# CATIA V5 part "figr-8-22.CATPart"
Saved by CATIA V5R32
Part number: Part1
Bounding box of the stored display mesh (mm): x -60 to 60, y -75 to 75, z 0 to 10
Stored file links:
  D:\PROJECTS\Project 2022\CATIA V5 6R 2022\Resources\Part Files\c08_catia_v5_6r2022_prt\figr-8-22.CATPart
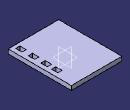
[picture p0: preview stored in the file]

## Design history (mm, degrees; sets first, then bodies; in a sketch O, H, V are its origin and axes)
Body1 (main body)
  Sketch1 on xy-plane, origin (0, 0, 0), H (1, 0, 0), V (0, 1, 0)
    line L1 (60, 75) -> (60, -75)
    line L2 (60, -75) -> (-60, -75)
    line L3 (-60, -75) -> (-60, 75)
    line L4 (-60, 75) -> (60, 75)
    length L2 = 120
    length L1 = 150
    vertical: L1 V, L3 V
    horizontal: L2 H, L4 H
    equidistance: L1 L3 O, L2 L4 O
  Pad1: profile Sketch1, direction (0, 0, 1), length 10
  Sketch2 on end face of Pad1, origin (0, 0, 10), H (1, 0, 0), V (0, 1, 0)
    point P1 (45, -59.5)
    line L1 (50, -52) -> (50, -67)
    line L2 (50, -67) -> (40, -67)
    line L3 (40, -67) -> (40, -52)
    line L4 (40, -52) -> (50, -52)
    reference projected line E1 (-60, -75) -> (60, -75) from edge [face of Pad1 from Sketch1.L2 | end face of Pad1]
    reference projected line E2 (60, -75) -> (60, 75) from edge [face of Pad1 from Sketch1.L1 | end face of Pad1]
    distance L2 E1 = 8
    distance L1 E2 = 10
    length L4 = 10
    length L3 = 15
    vertical: L1 V, L3 V
    horizontal: L2 H, L4 H
    equidistance: L1 L3 P1, L2 L4 P1
  Pocket1: profile Sketch2, direction (0, 0, -1), length 10
  RectPattern1: of Pocket1, direction 1 instances 4, spacing 20, along edge [face of Pad1 from Sketch1.L1 | end face of Pad1]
